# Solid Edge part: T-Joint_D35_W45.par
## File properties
Author: hStrempfl
Template: iso metric part.par
Last saved by: fknapp
Revision: 155
Application: Solid Edge
Username: hStrempfl
Genauigkeit: 0,990
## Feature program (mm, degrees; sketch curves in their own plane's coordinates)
sketch for "unnamed Protrusion 1" plane through (0, 0, 0) normal (0, 0, 1) x-axis (1, 0, 0)
  line (19.8, 16.8695) -> (-15, 16.8695)
  line (-15, 16.8695) -> (-15, -17.9305)
  line (-15, -17.9305) -> (19.8, -17.9305)
  line (19.8, -17.9305) -> (19.8, 16.8695)
  dimension (linear) = 15
  dimension (linear) = 19.8
extrude "unnamed Protrusion 1" add finite 16 along +normal
chamfer "Fase_2" setback 13  SetBackValue2 = 45 deg
sketch for "Bohrung_1" plane through (0, -13.0722, 7.8583) normal (0, -0.707107, 0.707107) x-axis (1, 0, 0)
  hole centre (2.4, 2.5331) bore radius 6.25
hole "Bohrung_1" diameter 12.5 through  CounterSinkAngle = 90 deg
fillet "Verrundung_2" radius 17.4
sketch for "Bohrung_2" plane through (-0.1, 6.1215, 16) normal (0, 0, 1) x-axis (1, 0, 0)
hole "Bohrung_2" diameter 6.2 through  CounterSinkAngle = 90 deg
sketch for "unnamed Hole 1" plane through (-0.1, 6.1215, 16) normal (0, 0, 1) x-axis (1, 0, 0)
hole "unnamed Hole 1" through
pattern "unnamed Pattern 1" of "Bohrung_2", "unnamed Hole 1"
fillet "Verrundung_4" radius 0.5
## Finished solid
Body 1: solid body, 12 faces, 23 edges, 10 vertices.
  Faces by surface: cylinder 4, cone 3, plane 3, torus 2
  Edges by curve: circle 12, intersection 5, line 4, ellipse 2
Bounding box of the edges (mm; curved faces can reach further): 34.800 x 34.800 x 16.000, from (-15, -17.9305, 0) to (19.8, 16.8695, 16).
Cylindrical faces by radius (mm): R3.1 x2, R6.25 x1, R17.4 x1
Conical faces (half-angle, radius in mm at the cone's reference point): 45 deg R6 x2, 45 deg R9 x1
Toroidal faces (ring radius, tube radius in mm): R16.9 r0.5 x2
Planar faces by outward normal: +z 1, -z 1, oblique 1
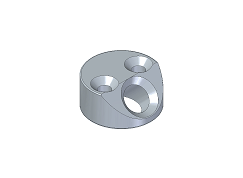
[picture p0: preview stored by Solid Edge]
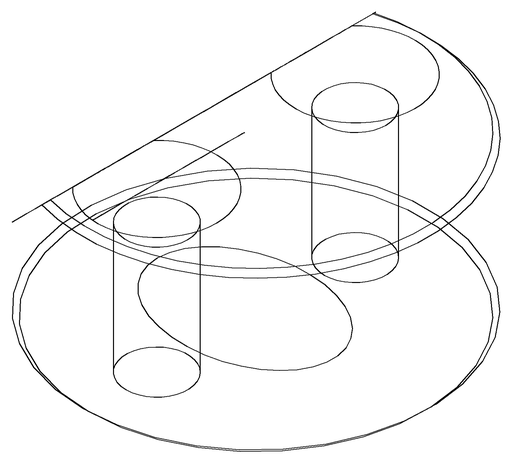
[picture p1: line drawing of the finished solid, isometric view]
